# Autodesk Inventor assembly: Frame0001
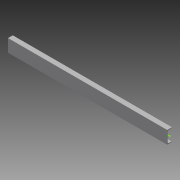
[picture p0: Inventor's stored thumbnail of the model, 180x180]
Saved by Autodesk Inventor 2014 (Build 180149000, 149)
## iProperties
Created: 2009-11
Part Number: Frame0001
Document SubType Name: Assembly
Designer: pokornp
_FrameDoc: Frame Assembly
_Version: 15.0.0
Author: pokornp
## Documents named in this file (3)
- C:\Users\iTools\Desktop\tutorial files\Frame Analysis 1\side1\Frame\Frame0001.iam
- C:\Users\iTools\Desktop\tutorial files\Frame Analysis 1\side1\Frame\Skeleton0001.ipt
- C:\Users\iTools\Desktop\tutorial files\Frame Analysis 1\side1\Frame\DIN U 200 00000001.ipt
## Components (2 placed, 2 different names)
1. Frame Reference Model
2. DIN U 200 00000001:1
